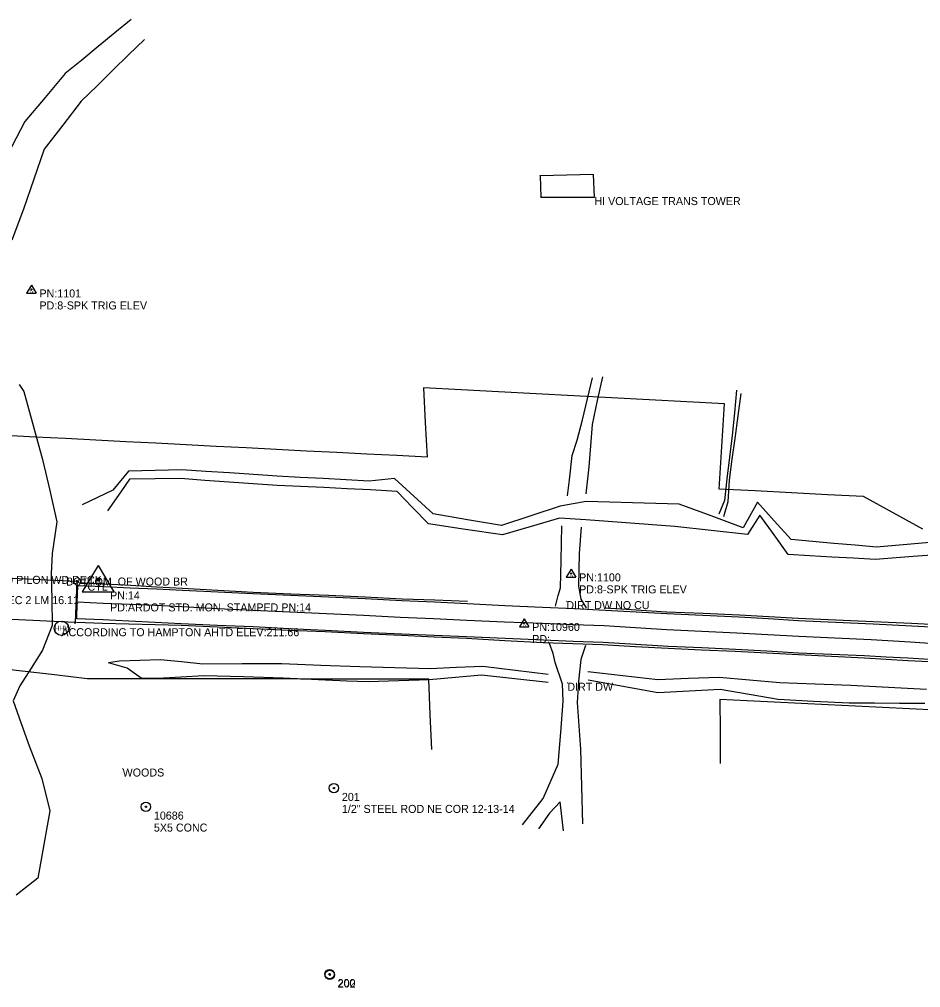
# Model space of a CAD drawing. Extents: x 1138803 to 1169983, y 1655906 to 1658226.
# Drawn here: x 1164922 to 1165485, y 1656502 to 1657107 of the extents above; entities that cross this region are included whole.
import ezdxf

# ---------------------------------------------------------------- set-up
doc = ezdxf.new("R2010")
doc.units = 0
for name, color, linetype in [('S_BRIDGE', 7, 'Continuous'), ('S_BRIDGE_ANNOT', 7, 'Continuous'), ('S_DITCHLINE', 7, 'Continuous'), ('S_DRIVEWAY', 7, 'Continuous'), ('S_EDGE_PAVEMENT', 7, 'Continuous'), ('S_HIST_HIGH_WATER', 7, 'Continuous'), ('S_HIST_HIGH_WATER_ANNOT', 7, 'Continuous'), ('S_IRON_PIN', 7, 'Continuous'), ('S_IRON_PIN_ANNOT', 7, 'Continuous'), ('S_LOG_MILE_ANNOT', 7, 'Continuous'), ('S_MISC_STRUCTURES', 7, 'Continuous'), ('S_MISC_STRUCTURES_ANNOT', 7, 'Continuous'), ('S_MSC_PT_SYM', 7, 'Continuous'), ('S_PAVEMENT_CROWN', 7, 'Continuous'), ('S_PRIMARY_CTL', 7, 'Continuous'), ('S_PRIMARY_CTL_ANNOT', 7, 'Continuous'), ('S_SECONDARY_CTL', 7, 'Continuous'), ('S_SECONDARY_CTL_ANNOT', 7, 'Continuous'), ('S_SHOULDER', 7, 'Continuous'), ('S_STR_PT_SYM', 7, 'Continuous'), ('S_STREAM', 7, 'Continuous'), ('S_SURVEY_TEXT_ANNOT', 7, 'Continuous'), ('S_TREE', 7, 'Continuous'), ('S_UTL_PT_SYM', 7, 'Continuous')]:
    doc.layers.add(name, color=color, linetype=linetype)

msp = doc.modelspace()

# ---------------------------------------------------------------- linework, layer by layer
at = {"layer": 'S_BRIDGE'}
for p, q in [((1164881.2, 1656759.11), (1164957.76, 1656755.87)), ((1164957.76, 1656755.87), (1164956.58, 1656729.86)), ((1164956.58, 1656729.86), (1164879.69, 1656733.51))]:
    msp.add_line(p, q, dxfattribs=at)
at = {"layer": 'S_DITCHLINE'}
for points in [[(1165369.9, 1656875.05), (1165368.51, 1656860.89), (1165367.12, 1656846.72), (1165365.41, 1656833.25), (1165363.71, 1656819.78), (1165362.24, 1656806.17), (1165358.83, 1656797.71)], [(1165372.61, 1656873.11), (1165370.66, 1656859.03), (1165368.71, 1656844.94), (1165366.98, 1656831.96), (1165365.25, 1656818.99), (1165364.41, 1656805.3), (1165361.58, 1656796.04)], [(1165500.07, 1656780.72), (1165478.62, 1656778.89), (1165457.17, 1656777.06), (1165443.86, 1656778.22), (1165430.56, 1656779.39), (1165417.25, 1656780.55), (1165403.94, 1656781.72), (1165393.38, 1656793.45), (1165382.83, 1656805.18), (1165373.97, 1656789.19), (1165353.95, 1656796.58), (1165333.93, 1656803.96), (1165319.41, 1656804.36), (1165304.89, 1656804.76), (1165290.38, 1656805.16), (1165275.86, 1656805.56), (1165259.65, 1656802.7), (1165241.32, 1656796.66), (1165222.99, 1656790.62), (1165201.65, 1656794.21), (1165180.31, 1656797.79), (1165168.23, 1656808.85), (1165156.15, 1656819.91), (1165140.32, 1656818.24), (1165125.95, 1656819.04), (1165111.59, 1656819.84), (1165097.22, 1656820.64), (1165082.86, 1656821.43), (1165067.98, 1656822.4), (1165053.11, 1656823.37), (1165038.23, 1656824.34), (1165023.35, 1656825.31), (1165006.68, 1656824.91), (1164990.01, 1656824.51), (1164980.22, 1656812.68), (1164961.02, 1656803.46)], [(1165503.73, 1656772.96), (1165480.09, 1656771.15), (1165456.45, 1656769.33), (1165442.86, 1656770.09), (1165429.27, 1656770.85), (1165415.69, 1656771.61), (1165402.1, 1656772.37), (1165393.29, 1656784.73), (1165384.48, 1656797.09), (1165376.74, 1656784.91), (1165353.99, 1656787.44), (1165331.24, 1656789.98), (1165317.36, 1656791.01), (1165303.48, 1656792.04), (1165289.59, 1656793.07), (1165275.71, 1656794.11), (1165259.28, 1656795.25), (1165241.49, 1656790.03), (1165223.69, 1656784.81), (1165200.54, 1656788.16), (1165177.39, 1656791.52), (1165167.55, 1656801.63), (1165157.71, 1656811.74), (1165141.22, 1656812.88), (1165126.65, 1656813.55), (1165112.07, 1656814.22), (1165097.5, 1656814.9), (1165082.93, 1656815.57), (1165067.84, 1656816.63), (1165052.76, 1656817.7), (1165037.67, 1656818.77), (1165022.58, 1656819.84), (1165006.55, 1656819.63), (1164990.51, 1656819.43), (1164985.1, 1656811.53), (1164976.88, 1656799.67)], [(1165252.24, 1656692.37), (1165231.41, 1656694.71), (1165210.59, 1656697.05), (1165194.22, 1656695.62), (1165177.85, 1656694.18), (1165158.77, 1656693.49), (1165139.68, 1656692.79), (1165126.39, 1656693.4), (1165113.1, 1656694.02), (1165099.81, 1656694.63), (1165086.52, 1656695.24), (1165061.72, 1656695.95), (1165036.93, 1656696.66), (1165022.65, 1656695.78), (1165008.37, 1656694.9), (1164997.87, 1656695.11), (1164989.1, 1656701.37), (1164977.36, 1656704.75)], [(1165252.22, 1656697.57), (1165231.81, 1656700.07), (1165211.41, 1656702.56), (1165194.87, 1656701.79), (1165178.32, 1656701.01), (1165156.43, 1656701.59), (1165134.53, 1656702.18), (1165110.12, 1656703.16), (1165085.72, 1656704.14), (1165061.06, 1656704.04), (1165036.41, 1656703.94), (1165023.04, 1656705.28), (1165009.68, 1656706.62), (1164997.02, 1656706.21), (1164984.36, 1656705.79), (1164977.4, 1656704.79)], [(1165488.53, 1656688.11), (1165472.74, 1656688.92), (1165456.95, 1656689.74), (1165441.16, 1656690.55), (1165419.03, 1656691.36), (1165396.91, 1656692.16), (1165377.95, 1656693.9), (1165358.99, 1656695.64), (1165339.85, 1656694.93), (1165320.72, 1656694.22), (1165298.83, 1656696.62), (1165276.94, 1656699.03)], [(1165487.49, 1656679.27), (1165471.72, 1656679.39), (1165455.95, 1656679.51), (1165440.18, 1656679.63), (1165417.98, 1656680.69), (1165395.79, 1656681.76), (1165377.75, 1656684.94), (1165359.7, 1656688.13), (1165340.2, 1656687.1), (1165320.7, 1656686.08), (1165298.91, 1656690.02), (1165277.13, 1656693.96)]]:
    msp.add_lwpolyline(points, dxfattribs=at)
at = {"layer": 'S_DRIVEWAY'}
for points in [[(1165285.99, 1656883.53), (1165282.79, 1656868.63), (1165279.59, 1656853.73), (1165278.61, 1656840.43), (1165277.62, 1656827.13), (1165275.76, 1656810.33)], [(1165264.29, 1656809.17), (1165265.43, 1656819.06), (1165267.24, 1656834.21), (1165270.29, 1656843.84), (1165273.57, 1656856.59), (1165276.69, 1656869.73), (1165279.82, 1656882.88)], [(1165256.76, 1656740.26), (1165258.49, 1656746.86), (1165259.84, 1656751.6), (1165260.18, 1656768.78), (1165260.74, 1656790.46)], [(1165272.8, 1656789.49), (1165271.52, 1656773.14), (1165271.04, 1656752.7), (1165272.63, 1656744.52), (1165275.98, 1656739.04)], [(1165236.15, 1656603.57), (1165249.06, 1656619.96), (1165258.42, 1656641.52), (1165259.98, 1656661.13), (1165261.54, 1656680.74), (1165261.02, 1656691.48), (1165256.57, 1656705.03), (1165255.29, 1656710.51), (1165252.89, 1656716.86)], [(1165275.57, 1656715.66), (1165272.61, 1656706.85), (1165271.19, 1656693.25), (1165270.34, 1656679.94), (1165271.35, 1656665.35), (1165272.36, 1656650.76), (1165272.96, 1656627.46), (1165273.57, 1656604.15)], [(1165261.64, 1656599.83), (1165259.61, 1656617.96), (1165252.99, 1656610.92), (1165246.05, 1656600.94)]]:
    msp.add_lwpolyline(points, dxfattribs=at)
at = {"layer": 'S_EDGE_PAVEMENT'}
for points in [[(1165490.18, 1656706.86), (1165476.74, 1656707.61), (1165463.3, 1656708.36), (1165449.86, 1656709.1), (1165429.19, 1656709.98), (1165408.52, 1656710.86), (1165388.82, 1656711.97), (1165369.12, 1656713.07), (1165348.18, 1656714.04), (1165327.24, 1656715.01), (1165306.83, 1656716.23), (1165286.43, 1656717.45), (1165267.85, 1656718.16), (1165249.27, 1656718.87), (1165225.18, 1656719.97), (1165201.1, 1656721.07), (1165180.88, 1656721.85), (1165160.66, 1656722.63), (1165136.73, 1656723.8), (1165112.81, 1656724.98), (1165090.34, 1656726.06), (1165067.86, 1656727.15), (1165045.38, 1656728.17), (1165022.9, 1656729.2), (1165006.57, 1656729.98), (1164990.25, 1656730.77), (1164973.93, 1656731.55), (1164957.61, 1656732.34), (1164957.79, 1656742.54), (1164958.25, 1656752.86)], [(1165503.38, 1656726.49), (1165479.25, 1656727.75), (1165455.11, 1656729.01), (1165431.73, 1656730.03), (1165408.36, 1656731.04), (1165389.83, 1656732.21), (1165371.31, 1656733.38), (1165348.79, 1656734.4), (1165326.28, 1656735.43), (1165307.12, 1656736.49), (1165287.96, 1656737.55), (1165268.29, 1656738.43), (1165248.62, 1656739.31), (1165225.13, 1656740.47), (1165201.64, 1656741.64), (1165181.21, 1656742.58), (1165160.78, 1656743.52), (1165137.88, 1656744.66), (1165114.98, 1656745.8), (1165091.29, 1656746.78), (1165067.61, 1656747.77), (1165045.7, 1656748.88), (1165023.78, 1656749.99), (1165007.4, 1656750.71), (1164991.03, 1656751.43), (1164974.65, 1656752.14), (1164958.27, 1656752.86)]]:
    msp.add_lwpolyline(points, dxfattribs=at)
at = {"layer": 'S_HIST_HIGH_WATER'}
msp.add_circle((1164948.03, 1656726.38), 4.5, dxfattribs=at)
at = {"layer": 'S_IRON_PIN'}
for centre, radius in [((1165118.27, 1656626.48), 2.91), ((1165118.27, 1656626.48), 0.411), ((1165118.27, 1656626.48), 0.262), ((1165118.27, 1656626.48), 0.212), ((1165118.27, 1656626.48), 0.145), ((1165118.27, 1656626.48), 0.0822), ((1165118.27, 1656626.48), 0.0581), ((1165000.83, 1656614.82), 2.91), ((1165000.83, 1656614.82), 0.411), ((1165000.83, 1656614.82), 0.262), ((1165000.83, 1656614.82), 0.212), ((1165000.83, 1656614.82), 0.145), ((1165000.83, 1656614.82), 0.0822), ((1165000.83, 1656614.82), 0.0581), ((1165115.57, 1656510.18), 2.91), ((1165115.73, 1656509.89), 2.91), ((1165115.57, 1656510.18), 0.411), ((1165115.57, 1656510.18), 0.262), ((1165115.73, 1656509.89), 0.411), ((1165115.57, 1656510.18), 0.212), ((1165115.57, 1656510.18), 0.145), ((1165115.73, 1656509.89), 0.262), ((1165115.57, 1656510.18), 0.0822), ((1165115.57, 1656510.18), 0.0581), ((1165115.73, 1656509.89), 0.212), ((1165115.73, 1656509.89), 0.145), ((1165115.73, 1656509.89), 0.0822), ((1165115.73, 1656509.89), 0.0581)]:
    msp.add_circle(centre, radius, dxfattribs=at)
at = {"layer": 'S_MISC_STRUCTURES'}
for p, q in [((1165280.48, 1657009.86), (1165247.16, 1657009.13)), ((1165247.16, 1657009.13), (1165247.61, 1656995.77)), ((1165281.04, 1656995.77), (1165280.48, 1657009.86)), ((1165247.61, 1656995.77), (1165281.04, 1656995.77))]:
    msp.add_line(p, q, dxfattribs=at)
at = {"layer": 'S_MSC_PT_SYM'}
for points in [[(1165247.16, 1657009.13), (1165247.16, 1657009.18), (1165247.16, 1657009.13), (1165247.11, 1657009.13), (1165247.16, 1657009.13), (1165247.16, 1657009.08), (1165247.16, 1657009.13), (1165247.21, 1657009.13)], [(1165280.48, 1657009.86), (1165280.48, 1657009.91), (1165280.48, 1657009.86), (1165280.43, 1657009.86), (1165280.48, 1657009.86), (1165280.48, 1657009.81), (1165280.48, 1657009.86), (1165280.53, 1657009.86)], [(1165247.61, 1656995.77), (1165247.61, 1656995.82), (1165247.61, 1656995.77), (1165247.56, 1656995.77), (1165247.61, 1656995.77), (1165247.61, 1656995.72), (1165247.61, 1656995.77), (1165247.66, 1656995.77)], [(1165281.04, 1656995.77), (1165281.04, 1656995.82), (1165281.04, 1656995.77), (1165280.99, 1656995.77), (1165281.04, 1656995.77), (1165281.04, 1656995.72), (1165281.04, 1656995.77), (1165281.09, 1656995.77)], [(1164950.92, 1656758.04), (1164950.92, 1656758.09), (1164950.92, 1656758.04), (1164950.87, 1656758.04), (1164950.92, 1656758.04), (1164950.92, 1656757.99), (1164950.92, 1656758.04), (1164950.97, 1656758.04)], [(1165263.49, 1656743.32), (1165263.49, 1656743.37), (1165263.49, 1656743.32), (1165263.44, 1656743.32), (1165263.49, 1656743.32), (1165263.49, 1656743.27), (1165263.49, 1656743.32), (1165263.54, 1656743.32)], [(1165267.65, 1656728.05), (1165267.65, 1656728.1), (1165267.65, 1656728.05), (1165267.6, 1656728.05), (1165267.65, 1656728.05), (1165267.65, 1656728), (1165267.65, 1656728.05), (1165267.7, 1656728.05)], [(1165298.17, 1656726.8), (1165298.17, 1656726.85), (1165298.17, 1656726.8), (1165298.12, 1656726.8), (1165298.17, 1656726.8), (1165298.17, 1656726.76), (1165298.17, 1656726.8), (1165298.22, 1656726.8)], [(1165264.12, 1656692.31), (1165264.12, 1656692.36), (1165264.12, 1656692.31), (1165264.07, 1656692.31), (1165264.12, 1656692.31), (1165264.12, 1656692.26), (1165264.12, 1656692.31), (1165264.17, 1656692.31)], [(1164986.28, 1656638.73), (1164986.28, 1656638.78), (1164986.28, 1656638.73), (1164986.23, 1656638.73), (1164986.28, 1656638.73), (1164986.28, 1656638.68), (1164986.28, 1656638.73), (1164986.33, 1656638.73)]]:
    msp.add_lwpolyline(points, dxfattribs=at)
at = {"layer": 'S_PAVEMENT_CROWN'}
msp.add_lwpolyline([(1165502.76, 1656716.03), (1165478.31, 1656717.59), (1165453.86, 1656719.15), (1165431.3, 1656720.13), (1165408.74, 1656721.11), (1165389.35, 1656722.2), (1165369.96, 1656723.3), (1165348.16, 1656724.29), (1165326.36, 1656725.29), (1165306.73, 1656726.56), (1165287.09, 1656727.83), (1165267.84, 1656728.54), (1165248.58, 1656729.25), (1165224.92, 1656730.26), (1165201.26, 1656731.28), (1165180.46, 1656732.19), (1165159.67, 1656733.11), (1165136.69, 1656734.23), (1165113.71, 1656735.34), (1165090.77, 1656736.35), (1165067.82, 1656737.36), (1165045.52, 1656738.58), (1165023.22, 1656739.79), (1165006.87, 1656740.49), (1164990.53, 1656741.19), (1164974.18, 1656741.89), (1164957.83, 1656742.58)], dxfattribs=at)
at = {"layer": 'S_PRIMARY_CTL'}
for p, q in [((1164970.94, 1656765.59), (1164960.91, 1656749.08)), ((1164970.94, 1656765.59), (1164980.76, 1656749.08)), ((1164960.91, 1656749.08), (1164980.76, 1656749.08))]:
    msp.add_line(p, q, dxfattribs=at)
for radius in [1.04, 0.609, 0.344]:
    msp.add_circle((1164970.94, 1656756.89), radius, dxfattribs=at)
at = {"layer": 'S_SECONDARY_CTL'}
for p, q in [((1164929.32, 1656940.67), (1164926.31, 1656935.71)), ((1164929.32, 1656940.67), (1164932.26, 1656935.71)), ((1164926.31, 1656935.71), (1164932.26, 1656935.71)), ((1165266.49, 1656763.26), (1165263.48, 1656758.31)), ((1165266.49, 1656763.26), (1165269.44, 1656758.31)), ((1165263.48, 1656758.31), (1165269.44, 1656758.31)), ((1165237.17, 1656732.28), (1165234.16, 1656727.33)), ((1165237.17, 1656732.28), (1165240.12, 1656727.33)), ((1165234.16, 1656727.33), (1165240.12, 1656727.33))]:
    msp.add_line(p, q, dxfattribs=at)
for centre, radius in [((1164929.32, 1656938.06), 0.311), ((1164929.32, 1656938.06), 0.183), ((1164929.32, 1656938.06), 0.103), ((1165266.49, 1656760.65), 0.311), ((1165266.49, 1656760.65), 0.183), ((1165266.49, 1656760.65), 0.103), ((1165237.17, 1656729.67), 0.311), ((1165237.17, 1656729.67), 0.183), ((1165237.17, 1656729.67), 0.103)]:
    msp.add_circle(centre, radius, dxfattribs=at)
at = {"layer": 'S_SHOULDER'}
for points in [[(1165201.79, 1656743.05), (1165181.32, 1656743.85), (1165160.84, 1656744.64), (1165137.85, 1656745.7), (1165114.86, 1656746.75), (1165091.4, 1656747.76), (1165067.94, 1656748.78), (1165045.85, 1656749.98), (1165023.75, 1656751.19), (1165007.54, 1656752.09), (1164991.33, 1656752.98), (1164975.12, 1656753.88), (1164958.9, 1656754.78)], [(1165503.13, 1656728.14), (1165479.15, 1656729.24), (1165455.18, 1656730.33), (1165431.77, 1656731.4), (1165408.36, 1656732.47), (1165390.04, 1656733.51), (1165371.73, 1656734.56), (1165348.94, 1656735.48), (1165326.14, 1656736.4), (1165307.15, 1656737.64), (1165288.17, 1656738.88)], [(1165490.37, 1656705.28), (1165476.83, 1656706.06), (1165463.28, 1656706.84), (1165449.74, 1656707.61), (1165429.16, 1656708.64), (1165408.59, 1656709.66), (1165388.74, 1656710.7), (1165368.9, 1656711.74), (1165347.96, 1656712.69), (1165327.02, 1656713.65), (1165306.51, 1656714.82), (1165286, 1656715.98), (1165267.48, 1656716.64), (1165248.97, 1656717.3), (1165225.07, 1656718.59), (1165201.18, 1656719.88), (1165180.88, 1656720.81), (1165160.59, 1656721.74), (1165136.74, 1656722.9), (1165112.89, 1656724.07), (1165090.33, 1656725.05), (1165067.77, 1656726.03), (1165045.36, 1656727.08), (1165022.96, 1656728.13), (1165006.57, 1656728.56), (1164990.18, 1656729), (1164973.79, 1656729.43), (1164957.39, 1656729.87)]]:
    msp.add_lwpolyline(points, dxfattribs=at)
at = {"layer": 'S_STR_PT_SYM'}
for points in [[(1164957.76, 1656755.87), (1164957.76, 1656756.37), (1164957.76, 1656755.87), (1164957.26, 1656755.87), (1164957.76, 1656755.87), (1164957.76, 1656755.37), (1164957.76, 1656755.87), (1164958.26, 1656755.87)], [(1164956.58, 1656729.86), (1164956.58, 1656730.36), (1164956.58, 1656729.86), (1164956.08, 1656729.86), (1164956.58, 1656729.86), (1164956.58, 1656729.36), (1164956.58, 1656729.86), (1164957.08, 1656729.86)]]:
    msp.add_lwpolyline(points, dxfattribs=at)
at = {"layer": 'S_STREAM'}
for points in [[(1164991.68, 1657106.81), (1164981.36, 1657098.34), (1164971.05, 1657089.87), (1164960.74, 1657081.4), (1164950.42, 1657072.94), (1164937.84, 1657057.95), (1164925.26, 1657042.97), (1164914.27, 1657022.13)], [(1164999.86, 1657094.21), (1164990.01, 1657084.6), (1164980.16, 1657074.99), (1164970.31, 1657065.38), (1164960.47, 1657055.77), (1164948.86, 1657040.76), (1164937.26, 1657025.75), (1164930.79, 1657007), (1164924.33, 1656988.25), (1164917.16, 1656968.82)], [(1164921.55, 1656878.57), (1164924.67, 1656874.35), (1164930.49, 1656853.12), (1164936.3, 1656831.88), (1164940.74, 1656812.36), (1164945.18, 1656792.83), (1164942.29, 1656773.15), (1164941.64, 1656760.44), (1164942, 1656744.31), (1164942.36, 1656728.17), (1164936.19, 1656712.65), (1164929.13, 1656701.52), (1164922.07, 1656690.39), (1164917.94, 1656681), (1164922.87, 1656666.92), (1164927.8, 1656652.84), (1164935.81, 1656632.45), (1164940.74, 1656612.29), (1164937.01, 1656591.21), (1164933.27, 1656570.12), (1164919.81, 1656559.57)]]:
    msp.add_lwpolyline(points, dxfattribs=at)
at = {"layer": 'S_TREE'}
for points in [[(1165486.25, 1656788.28), (1165467.68, 1656798.47), (1165449.11, 1656808.66), (1165426.59, 1656809.83), (1165404.07, 1656811), (1165381.55, 1656812.16), (1165359.03, 1656813.33), (1165359.84, 1656826.62), (1165360.64, 1656839.91), (1165361.45, 1656853.2), (1165362.25, 1656866.49), (1165338.74, 1656867.75), (1165315.23, 1656869.02), (1165291.73, 1656870.28), (1165268.22, 1656871.55), (1165244.71, 1656872.81), (1165221.21, 1656874.07), (1165197.7, 1656875.34), (1165174.19, 1656876.6), (1165175.33, 1656854.92), (1165176.47, 1656833.23), (1165157.65, 1656834.2), (1165138.83, 1656835.17), (1165120.01, 1656836.14), (1165101.2, 1656837.1), (1165082.38, 1656838.07), (1165063.56, 1656839.04), (1165044.74, 1656840.01), (1165025.92, 1656840.98), (1165007.11, 1656841.94), (1164988.29, 1656842.91), (1164969.47, 1656843.88), (1164950.65, 1656844.85), (1164931.83, 1656845.81), (1164913.02, 1656846.78)], [(1165179.39, 1656650.53), (1165178.45, 1656672.54), (1165177.5, 1656694.55), (1165164.17, 1656694.57), (1165150.83, 1656694.58), (1165137.49, 1656694.6), (1165124.15, 1656694.62), (1165110.81, 1656694.64), (1165097.48, 1656694.65), (1165084.14, 1656694.67), (1165070.8, 1656694.69), (1165057.46, 1656694.7), (1165044.12, 1656694.72), (1165030.79, 1656694.74), (1165017.45, 1656694.76), (1165004.11, 1656694.77), (1164990.77, 1656694.79), (1164977.43, 1656694.81), (1164964.1, 1656694.82), (1164943.76, 1656697.16), (1164923.43, 1656699.5), (1164903.09, 1656701.84)], [(1165494.85, 1656675.21), (1165477.92, 1656676.03), (1165461, 1656676.85), (1165444.07, 1656677.67), (1165427.15, 1656678.49), (1165410.22, 1656679.31), (1165393.3, 1656680.13), (1165376.38, 1656680.95), (1165359.45, 1656681.77), (1165359.56, 1656661.83), (1165359.66, 1656641.89)]]:
    msp.add_lwpolyline(points, dxfattribs=at)
at = {"layer": 'S_UTL_PT_SYM'}
for points in [[(1165237.17, 1656729.67), (1165237.17, 1656729.72), (1165237.17, 1656729.67), (1165237.12, 1656729.67), (1165237.17, 1656729.67), (1165237.17, 1656729.62), (1165237.17, 1656729.67), (1165237.22, 1656729.67)], [(1165267.65, 1656728.05), (1165267.65, 1656728.1), (1165267.65, 1656728.05), (1165267.6, 1656728.05), (1165267.65, 1656728.05), (1165267.65, 1656728), (1165267.65, 1656728.05), (1165267.7, 1656728.05)], [(1165298.17, 1656726.8), (1165298.17, 1656726.85), (1165298.17, 1656726.8), (1165298.12, 1656726.8), (1165298.17, 1656726.8), (1165298.17, 1656726.76), (1165298.17, 1656726.8), (1165298.22, 1656726.8)]]:
    msp.add_lwpolyline(points, dxfattribs=at)

# ---------------------------------------------------------------- texts
at = {"layer": 'S_BRIDGE_ANNOT'}
msp.add_text('5 SPAN WD PILON WD DECK', height=5, dxfattribs=at).set_placement((1164881.2, 1656754.11))
at = {"layer": 'S_HIST_HIGH_WATER'}
msp.add_text('HHW', height=3, rotation=360, dxfattribs=at).set_placement((1164943.94, 1656724.88))
at = {"layer": 'S_HIST_HIGH_WATER_ANNOT'}
msp.add_text('ACCORDING TO HAMPTON AHTD ELEV:211.66', height=5, dxfattribs=at).set_placement((1164948.03, 1656721.38))
at = {"layer": 'S_IRON_PIN_ANNOT'}
for s, p in [('201', (1165123.27, 1656618.48)), ('10686', (1165005.83, 1656606.82)), ('1/2" STEEL ROD NE COR 12-13-14 ', (1165123.27, 1656610.98)), ('5X5 CONC', (1165005.83, 1656599.32)), ('200', (1165120.57, 1656502.18)), ('202', (1165120.73, 1656501.89))]:
    msp.add_text(s, height=5, dxfattribs=at).set_placement(p)
at = {"layer": 'S_LOG_MILE_ANNOT'}
msp.add_text('HWY 274 SEC 2 LM 16.11', height=5, dxfattribs=at).set_placement((1164879.5, 1656741.43))
at = {"layer": 'S_MISC_STRUCTURES_ANNOT'}
msp.add_text('HI VOLTAGE TRANS TOWER', height=5, dxfattribs=at).set_placement((1165281.04, 1656990.77))
at = {"layer": 'S_PRIMARY_CTL'}
msp.add_text('CTL', height=5, rotation=360, dxfattribs=at).set_placement((1164964.35, 1656749.82))
at = {"layer": 'S_PRIMARY_CTL_ANNOT'}
for s, p in [('PN:14', (1164978.44, 1656744.39)), ('PD:ARDOT STD. MON. STAMPED PN:14', (1164978.44, 1656736.89))]:
    msp.add_text(s, height=5, dxfattribs=at).set_placement(p)
at = {"layer": 'S_SECONDARY_CTL'}
for p in [(1164928.11, 1656936.05), (1165265.29, 1656758.64), (1165235.97, 1656727.66)]:
    msp.add_text('TV', height=1.5, rotation=360, dxfattribs=at).set_placement(p)
at = {"layer": 'S_SECONDARY_CTL_ANNOT'}
for s, p in [('PN:1101', (1164934.32, 1656933.06)), ('PD:8-SPK TRIG ELEV', (1164934.32, 1656925.56)), ('PN:1100', (1165271.49, 1656755.65)), ('PD:8-SPK TRIG ELEV', (1165271.49, 1656748.15)), ('PN:10960', (1165242.17, 1656724.67)), ('PD:', (1165242.17, 1656717.17))]:
    msp.add_text(s, height=5, dxfattribs=at).set_placement(p)
at = {"layer": 'S_SURVEY_TEXT_ANNOT'}
for s, p in [('BOTTOM  OF WOOD BR', (1164950.92, 1656753.04)), ('DIRT DW NO CU', (1165263.49, 1656738.32)), ('DIRT DW', (1165264.12, 1656687.31)), ('WOODS', (1164986.28, 1656633.73))]:
    msp.add_text(s, height=5, dxfattribs=at).set_placement(p)

doc.saveas('drawing.dxf')
